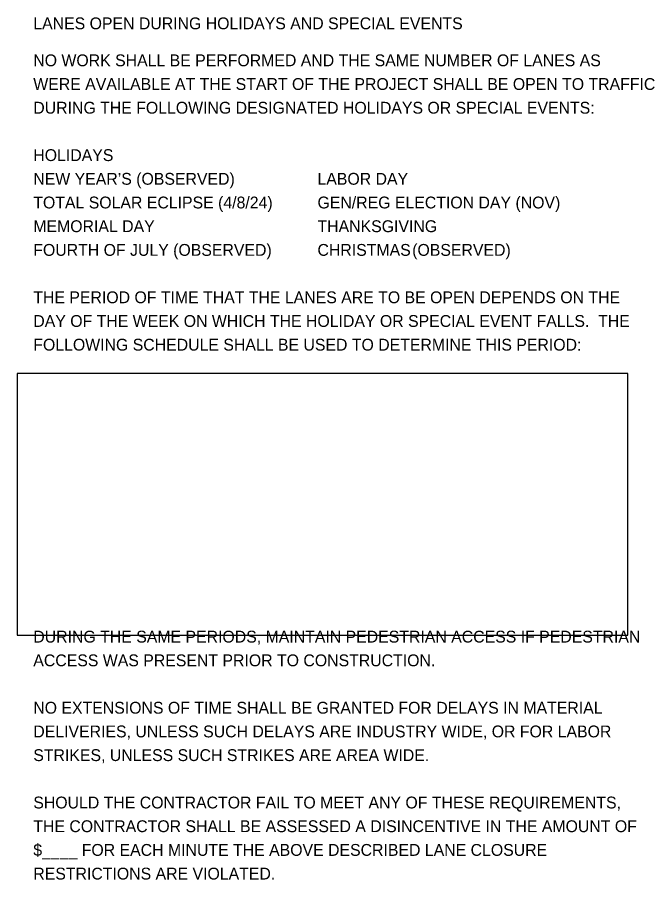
# Model space of a CAD drawing. Extents: x -1.3 to 43.7, y -2.4 to 22.
# Drawn here: x 36.2 to 43.74, y 1.49 to 11.68 of the extents above; entities that cross this region are included whole.
import ezdxf

# ---------------------------------------------------------------- set-up
doc = ezdxf.new("R2010")
doc.units = 0
doc.layers.add('SH_Text', color=7, linetype='Continuous')

msp = doc.modelspace()

# ---------------------------------------------------------------- linework, layer by layer
at = {"layer": 'SH_Text'}
msp.add_lwpolyline([(36.203, 4.378), (43.421, 4.378), (43.421, 7.472), (36.203, 7.472)], close=True, dxfattribs=at)

# ---------------------------------------------------------------- texts
for s, p in [('LANES OPEN DURING HOLIDAYS AND SPECIAL EVENTS', (36.393, 11.538)), ('NO WORK SHALL BE PERFORMED AND THE SAME NUMBER OF LANES AS ', (36.393, 11.101)), ('WERE AVAILABLE AT THE START OF THE PROJECT SHALL BE OPEN TO TRAFFIC ', (36.393, 10.821)), ('DURING THE FOLLOWING DESIGNATED HOLIDAYS OR SPECIAL EVENTS:', (36.393, 10.541)), ('HOLIDAYS', (36.393, 9.981)), ('NEW YEAR’S (OBSERVED)', (36.393, 9.701)), ('LABOR DAY', (39.753, 9.701)), ('TOTAL SOLAR ECLIPSE (4/8/24)', (36.393, 9.421)), ('GEN/REG ELECTION DAY (NOV)', (39.753, 9.421)), ('MEMORIAL DAY ', (36.393, 9.141)), ('THANKSGIVING', (39.753, 9.141)), ('FOURTH OF JULY (OBSERVED)', (36.393, 8.861)), ('CHRISTMAS', (39.753, 8.861)), ('(OBSERVED)', (40.873, 8.861)), ('THE PERIOD OF TIME THAT THE LANES ARE TO BE OPEN DEPENDS ON THE ', (36.393, 8.301)), ('DAY OF THE WEEK ON WHICH THE HOLIDAY OR SPECIAL EVENT FALLS.  THE ', (36.393, 8.021)), ('FOLLOWING SCHEDULE SHALL BE USED TO DETERMINE THIS PERIOD:', (36.393, 7.741)), ('DURING THE SAME PERIODS, MAINTAIN PEDESTRIAN ACCESS IF PEDESTRIAN ', (36.393, 4.291)), ('ACCESS WAS PRESENT PRIOR TO CONSTRUCTION. ', (36.393, 4.011)), ('NO EXTENSIONS OF TIME SHALL BE GRANTED FOR DELAYS IN MATERIAL ', (36.393, 3.451)), ('DELIVERIES, UNLESS SUCH DELAYS ARE INDUSTRY WIDE, OR FOR LABOR ', (36.393, 3.171)), ('STRIKES, UNLESS SUCH STRIKES ARE AREA WIDE.', (36.393, 2.891)), ('SHOULD THE CONTRACTOR FAIL TO MEET ANY OF THESE REQUIREMENTS, ', (36.393, 2.331)), ('THE CONTRACTOR SHALL BE ASSESSED A DISINCENTIVE IN THE AMOUNT OF ', (36.393, 2.051)), ('$____ FOR EACH MINUTE THE ABOVE DESCRIBED LANE CLOSURE ', (36.393, 1.771)), ('RESTRICTIONS ARE VIOLATED.', (36.393, 1.491))]:
    msp.add_text(s, height=0.14, dxfattribs=at).set_placement(p)

doc.saveas('drawing.dxf')
